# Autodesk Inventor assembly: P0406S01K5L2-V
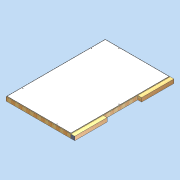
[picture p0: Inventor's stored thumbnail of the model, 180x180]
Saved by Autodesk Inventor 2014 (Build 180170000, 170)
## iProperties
Created: 2011-04
Part Number: P0406S01K5L2-V
Document SubType Name: Assembly
Designer: david.appleford
Description: 1w x 1.5w 01 Panel - 5 Locks 2 Lugs
Mass: 33000 g
Surface Area: 48578.3 cm^2
Volume: 167004 cm^3
Density: 0.1976 g/cm^3
Cost Center: £120.00
Justset: False
Author: david.appleford
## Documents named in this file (3)
- C:\Documents and Settings\john.everitt\Local Settings\My Documents\Vault\Production MkII\VIRTUAL ELEMENTS\Virtual Walls\Virtual Timber + MgO\P0406S01K5L2-V.iam
- C:\Documents and Settings\john.everitt\Local Settings\My Documents\Vault\Production MkII\VIRTUAL ELEMENTS\Virtual Lugs\Superceded Lugs\LA02C3V.ipt
- C:\Documents and Settings\john.everitt\Local Settings\My Documents\Vault\Production MkII\Virtual Elements\Virtual Walls\Virtual Timber + MgO\P0406S01K5-V.ipt
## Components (3 placed, 2 different names)
1. P0406S01K5-V:1 — Mate:1, Flush:1, Flush:2, Mate:7, Flush:11
2. LA02C3V:1 — Mate:1, Flush:1, Flush:2, Mate:9
3. LA02C3V:4 — Mate:7, Flush:11, Mate:9
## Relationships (6: Mate 3, Flush 3)
- Mate:1: P0406S01K5-V:1 ↔ LA02C3V:1
- Flush:1: P0406S01K5-V:1 ↔ LA02C3V:1
- Flush:2: P0406S01K5-V:1 ↔ LA02C3V:1
- Mate:7: P0406S01K5-V:1 ↔ LA02C3V:4
- Flush:11: P0406S01K5-V:1 ↔ LA02C3V:4
- Mate:9: LA02C3V:1 ↔ LA02C3V:4
## Named parameters: t = 1 mm, Cl = 2 mm
